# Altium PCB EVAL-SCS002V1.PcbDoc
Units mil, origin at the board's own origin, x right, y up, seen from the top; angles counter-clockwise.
Board outline 1200 x 440 mil, 2 copper layers (Top Layer, Bottom Layer), stack 61.855 mil thick; 32 components, 23 nets, 115 pads, 56 vias.
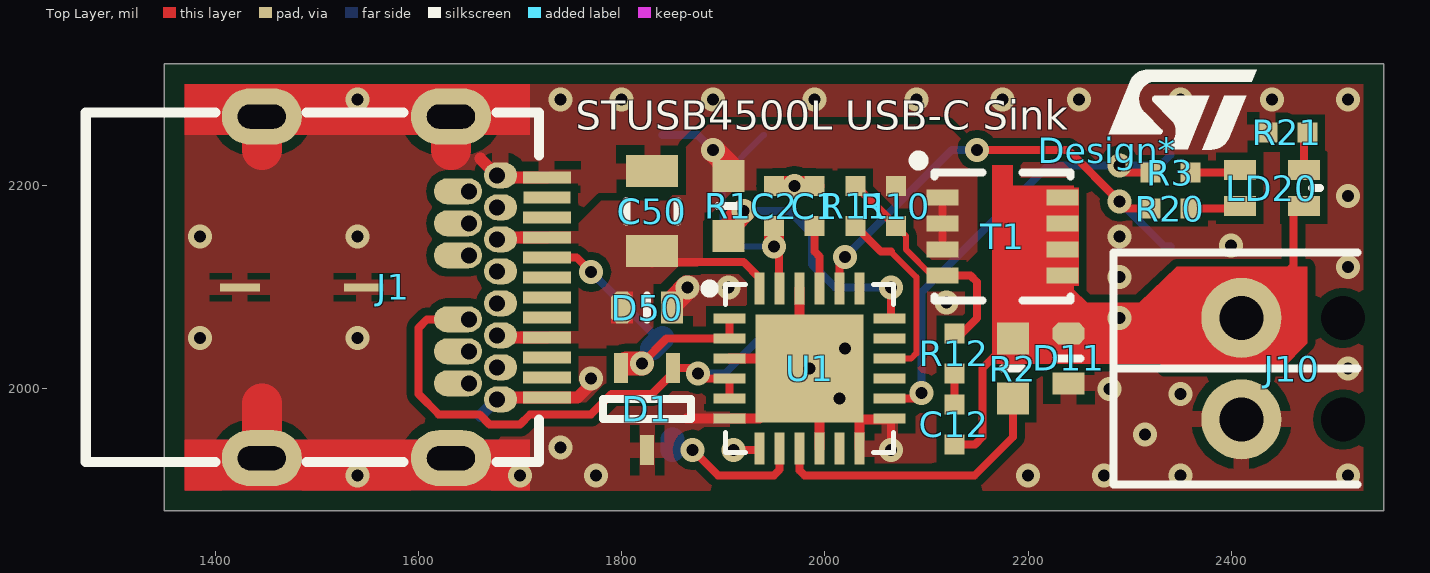
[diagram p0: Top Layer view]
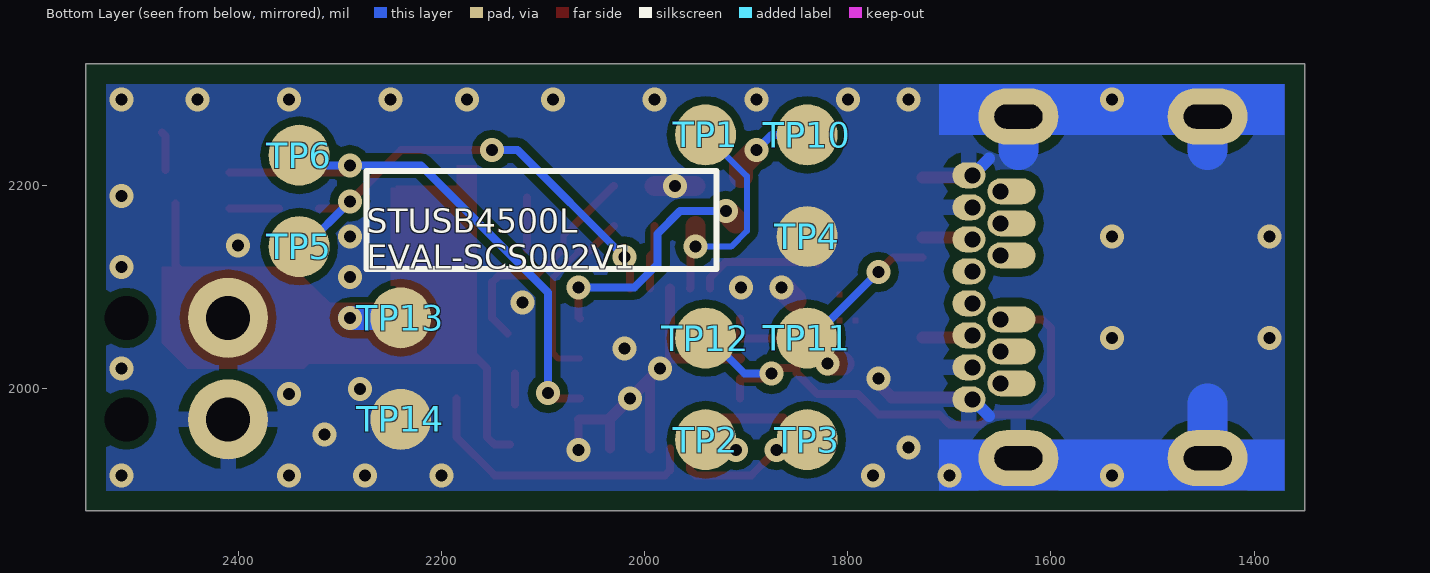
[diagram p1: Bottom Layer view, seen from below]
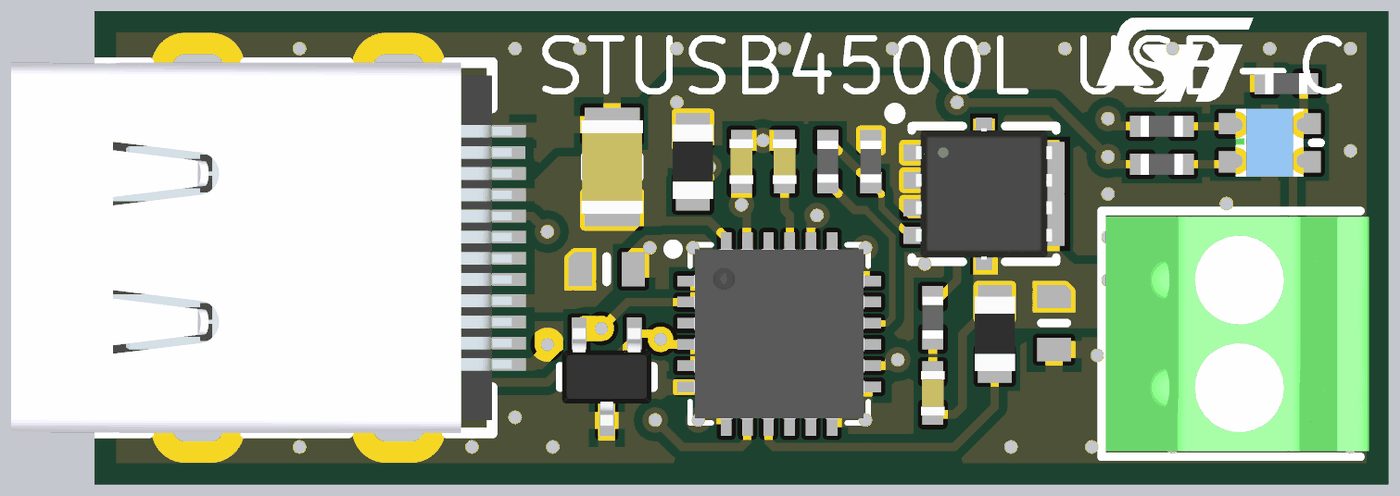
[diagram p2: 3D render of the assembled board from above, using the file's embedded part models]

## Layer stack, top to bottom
Top Solder: solder mask 0.4, Solder Resist, Dk 3.5
Top Layer: signal copper 1.4
Dielectric1: dielectric 59.0551, FR-4, Dk 4.8
Bottom Layer: signal copper 1.4
Bottom Solder: solder mask 0.4, Solder Resist, Dk 3.5

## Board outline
1350,1880 2550,1880 2550,2320 1350,2320

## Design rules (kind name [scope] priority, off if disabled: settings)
Clearance Clearance_USB [(InNet('DP') OR InNet('DM')) vs InNet('GND')] p1: gap=27.56 ignorepadtopadclearanceinfootprint=FALSE except(0: Arc-Hole Track-Hole SMDPad-Hole THPad-Hole Via-Hole Fill-Hole Poly-Hole Region-Hole Text-Hole)
Clearance Clearance_SMPSGND [InNet('GND') vs InNet('SMPSGND')] p2 off: gap=-39.37 ignorepadtopadclearanceinfootprint=FALSE except(0: Arc-Hole Track-Hole SMDPad-Hole THPad-Hole Via-Hole Fill-Hole Poly-Hole Region-Hole Text-Hole)
Clearance Clearance_SMPSGND_PLANE [IsCopperRegion] p3: gap=7.87 ignorepadtopadclearanceinfootprint=FALSE except(0: Arc-Hole Track-Hole SMDPad-Hole THPad-Hole Via-Hole Fill-Hole Poly-Hole Region-Hole Text-Hole)
Clearance [All] p4: gap=5.91 ignorepadtopadclearanceinfootprint=FALSE except(0: Arc-Hole Track-Hole SMDPad-Hole THPad-Hole Via-Hole Fill-Hole Poly-Hole Region-Hole Text-Hole)
ComponentClearance [All] p1 off: gap=10 collisioncheckmode=3 verticalgap=10 showdistances=FALSE
DiffPairsRouting [All] p1: maxlimit=39.37 minlimit=5.91 mostfreqgap=5.91 toplayer_minwidth=5.91 toplayer_maxwidth=118.11 toplayer_prefwidth=15.75 bottomlayer_minwidth=5.91 bottomlayer_maxwidth=118.11 bottomlayer_prefwidth=15.75 maxuncoupledlength=500
HoleSize [All] p1: absolutevalues=TRUE maxlimit=393.7 minlimit=11.81 maxpercent=80.000 minpercent=20.000
MinimumSolderMaskSliver [All] p1: minsoldermaskwidth=1
PlaneClearance PlaneClearance_USB [(InNet('DP') OR InNet('DM'))] p1: clearance=23.62
PlaneClearance [All] p2: clearance=5.91
PlaneConnect [All] p1: planeconnectstyle=Relief reliefexpansion=0 reliefentries=4 reliefconductorwidth=15.75 reliefairgap=5.91
PolygonConnect PolygonConnect_Screw [All vs (HasFootprint('SCREW M3 AND 20MM SPACER'))] p1: connectstyle=Direct reliefconductorwidth=11.81 reliefentries=4 polygonreliefangle="90 Angle" airgapwidth=7.87
PolygonConnect PolygonConnect_VIA [All vs IsVia] p2: connectstyle=Direct reliefconductorwidth=7.87 reliefentries=4 polygonreliefangle="45 Angle" airgapwidth=10
PolygonConnect PolygonConnect_VBUS [All vs InNet('VBUS')] p3: connectstyle=Direct reliefconductorwidth=15.75 reliefentries=4 polygonreliefangle="90 Angle" airgapwidth=10
PolygonConnect PolygonConnect_3V3 [All vs InNet('3V3')] p4: connectstyle=Direct reliefconductorwidth=7.87 reliefentries=4 polygonreliefangle="45 Angle" airgapwidth=10
PolygonConnect PolygonConnect_TP [(InComponentClass('Bottom Side Components'))] p5: connectstyle=Direct reliefconductorwidth=15.75 reliefentries=4 polygonreliefangle="90 Angle" airgapwidth=5.91
PolygonConnect [All] p6: connectstyle=Relief reliefconductorwidth=15.75 reliefentries=4 polygonreliefangle="90 Angle" airgapwidth=9.84
RoutingVias [All] p1: holewidth=11.81 width=23.62 viastyle="Through Hole" minholewidth=11.81 minwidth=23.62 maxholewidth=118.11 maxwidth=196.85
ShortCircuit ShortCircuit_SMPSGND [InNet('SMPSGND') vs InNet('GND')] p1: allowed=TRUE
ShortCircuit ShortCircuit_GNDA3 [InNet('GNDA3') vs InNet('GND')] p2: allowed=TRUE
ShortCircuit ShortCircuit_GNDA4 [InNet('GNDA4') vs InNet('GND')] p3: allowed=TRUE
ShortCircuit ShortCircuit_VCCINT34 [InNet('VCCINT34')] p4: allowed=TRUE
ShortCircuit ShortCircuit_VCCINT70 [InNet('VCCINT70') vs InNet('VCCINT')] p5: allowed=TRUE
ShortCircuit ShortCircuit_VCCINT84 [InNet('VCCINT84') vs InNet('VCCINT')] p6: allowed=TRUE
ShortCircuit ShortCircuit_VCCINT124 [InNet('VCCINT124') vs InNet('VCCINT')] p7: allowed=TRUE
ShortCircuit ShortCircuit_VCCINT138 [InNet('VCCINT138') vs InNet('VCCINT')] p8: allowed=TRUE
ShortCircuit ShortCircuit_VCCINT38 [InNet('VCCINT38') vs InNet('VCCINT')] p9: allowed=TRUE
ShortCircuit ShortCircuit_VCCD3 [InNet('VCCD3') vs InNet('VCCD')] p10: allowed=TRUE
ShortCircuit ShortCircuit_VCCD4 [InNet('VCCD4') vs InNet('VCCD')] p11: allowed=TRUE
ShortCircuit ShortCircuit_VCCA3 [InNet('VCCA3') vs InNet('VCCA')] p12: allowed=TRUE
ShortCircuit ShortCircuit_VCCA4 [InNet('VCCa4') vs InNet('VCCA')] p13: allowed=TRUE
ShortCircuit [All] p14: allowed=FALSE
SilkToSilkClearance [All] p1: silktosilkclearance=0
SilkToSolderMaskClearance [IsPad] p1: minsilkscreentomaskgap=0 clearancetoexposedcopper=TRUE
SolderMaskExpansion SolderMaskExpansion_via [IsVia] p1: expansion=-7.87
SolderMaskExpansion [All] p2: expansion=4
Width [All] p1: maxlimit=393.7 minlimit=5.91 preferedwidth=7.87 minimp=50.000000 maximp=50.000000 favimp=50.000000
21 further rules are at their usual default settings.

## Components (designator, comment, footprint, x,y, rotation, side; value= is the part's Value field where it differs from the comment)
C1 "1µF" CAPC1005N 1990,2180 r270 top
C2 "1µF" CAPC1005N 1950,2180 r270 top
C12 "100nF" CAPC1005N 2127.5,1965 r270 top
C50 "4.7µF" CAPC2012N 1830,2175 r90 top
D1 "ESDA25W" SOT323-3L 1825,1980 r270 top value="25V TRANSIL SOT323"
D11 "ESDA25P35" QFN1610 2240,2030 r90 top value=22V
D50 "ESDA25P35" QFN1610 1825,2080 r180 top value=22V
Design* "Comment" "LOGO - ST - 2mm" 2277.82,2235 r0 top
J1 "USB_3.1_TypeC_Receptacle_1.6mm" "USB3 C - SMT ET T - H - F - WURTH - 632723X00011" 1310,2100 r270 top
J10 "VSNK" MPT_0.5_2-2.54 2410,2020 r180 top
LD20 "RGB" LED_0606_RGB_WURTH 2440,2197.5 r180 top
R1 "1k" RESC1608N 1905,2180 r90 top
R2 "1k" RESC1608N 2185,2020 r270 top
R3 "22k" RESC1005N 2340,2212.93 r180 top
R10 "100k" RESC1005N 2070,2180 r270 top
R11 "22k" RESC1005N 2030,2180 r270 top
R12 "100" RESC1005N 2127.5,2035 r270 top
R20 "22k" RESC1005N 2340,2177.5 r180 top
R21 "33k" RESC1005N 2455.32,2252.5 r180 top
T1 "STL6P3LLH6" POWERFLAT_3.3X3.3_F 2175,2150 r270 top
TP1 "TestPoint" TestPoint_SMD_1.27mm#1 2010,2250 r180 bottom value=TestPoint_SMD
TP2 "TestPoint" TestPoint_SMD_1.27mm#2 1950,1950 r90 bottom value=TestPoint_SMD
TP3 "TestPoint" TestPoint_SMD_1.27mm#2 1850,1950 r90 bottom value=TestPoint_SMD
TP4 "TestPoint" TestPoint_SMD_1.27mm#3 1660,2145 r90 bottom value=TestPoint_SMD
TP5 "TestPoint" TestPoint_SMD_1.27mm#4 2150,2130 r90 bottom value=TestPoint_SMD
TP6 "TestPoint" TestPoint_SMD_1.27mm#4 2150,2220 r90 bottom value=TestPoint_SMD
TP10 "TestPoint" TestPoint_SMD_1.27mm#4 1650,2240 r90 bottom value=TestPoint_SMD
TP11 "TestPoint" TestPoint_SMD_1.27mm#5 1825,2055 r225 bottom value=TestPoint_SMD
TP12 "TestPoint" TestPoint_SMD_1.27mm#2 1950,2050 r90 bottom value=TestPoint_SMD
TP13 "TestPoint" TestPoint_SMD_1.27mm#6 2350,2050 r90 bottom value=TestPoint_SMD
TP14 "TestPoint" TestPoint_SMD_1.27mm#7 2250,1780 r90 bottom value=TestPoint_SMD
U1 "STUSB4500L" "QFN24 - 4X4MM - PITCH 0.5MM - EXPOSEDPAD" 1985,2020 r0 top value=STUSB4500

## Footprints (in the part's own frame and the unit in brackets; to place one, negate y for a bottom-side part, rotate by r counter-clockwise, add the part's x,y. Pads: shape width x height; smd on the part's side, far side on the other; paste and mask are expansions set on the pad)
CAPC1005N [mm] "Chip Capacitor, Body 1.0x0.5mm, IPC Medium Density"
  rect 0.5x0.5 smd: 1(-0.5,0) 2(0.5,0)
  body extent -0.52,-0.27 0.53,0.28, height 0.55
CAPC2012N [mm] "Chip Capacitor, Body 2.0x1.3mm, IPC Medium Density"
  rect 0.8x1.3 smd: 1(-1,0) 2(1,0)
  silkscreen extent -0.25,-0.64 0.25,0.64, body extent -1.1,-0.72 1.1,0.73, height 1.35
LED_0606_RGB_WURTH [mm] "Chip; Body 1.6 x 1.6 mm (LxW typ) WURTH"
  rect 0.8x0.5 smd: A(-0.8,0.45) BK(-0.8,-0.45) GK(0.8,-0.45) RK(0.8,0.45)
  silkscreen extent -1.2,0 -1,0, body extent -0.8,-0.8 0.8,0.8, height 0.4
"LOGO - ST - 2mm" [mil]
  silkscreen extent 1,1 147,79
MPT_0.5_2-2.54 [mm] "Screw  PCB terminal block, 2 positions 2.54mm pitch"
  round 0 hole 1.1: 01(-2.54,1.27) 02(-2.54,-1.27)
  round 2 hole 1.1: 1(0,1.27) 2(0,-1.27)
  silkscreen extent -2.9,-2.9 3.2,2.9, body extent -3.1,-2.77 3.1,2.77, height 8.5
POWERFLAT_3.3X3.3_F [mm] "PowerFLAT™ 3.3 x 3.3 type F"
  rect 0.4x0.8 smd: 1(-0.975,-1.5) 2(-0.325,-1.5) 3(0.325,-1.5) 4(0.975,-1.5) 5(0.975,1.5) 6(0.325,1.5) 7(-0.325,1.5) 8(-0.975,1.5)
  Top Layer region: 0,1.9 1.225,1.9 1.225,0.2 1.775,0.2 1.775,-0.2 0,-0.2
  Top Layer region: 0,1.9 -1.225,1.9 -1.225,0.2 -1.775,0.2 -1.775,-0.2 0,-0.2
  silkscreen extent -2.02,-2.22 1.6,1.7, body extent -1.55,-1.6 1.55,1.6, height 0.8
"QFN24 - 4X4MM - PITCH 0.5MM - EXPOSEDPAD" [mm] "QFN24 - 4X4mm - pitch 0.5mm - ExposedPAD"
  rect 2.7x2.7 smd: 0(0,0)
  rect 0.8x0.25 smd: 1(-2,1.25) 2(-2,0.75) 3(-2,0.25) 4(-2,-0.25) 5(-2,-0.75) 6(-2,-1.25) 13(2,-1.25) 14(2,-0.75) 15(2,-0.25) 16(2,0.25) 17(2,0.75) 18(2,1.25)
  rect 0.25x0.8 smd: 7(-1.25,-2) 8(-0.75,-2) 9(-0.25,-2) 10(0.25,-2) 11(0.75,-2) 12(1.25,-2) 19(1.25,2) 20(0.75,2) 21(0.25,2) 22(-0.25,2) 23(-0.75,2) 24(-1.25,2)
  silkscreen extent -2.6,-2.1 2.1,2.1, body extent -2,-2 2,2, height 1
QFN1610 [mm] "QFN 1610"
  oct 0.55x0.8 smd paste+0 mask+0.1: 1(0.625,0)
  rect 0.55x0.8 smd: 2(-0.625,0)
  Top Layer region: 0.35,0.25 0.5,0.25 0.5,0.4 0.35,0.4
  Top Layer region: 0.5,-0.4 0.5,-0.25 0.35,-0.25 0.35,-0.4
  Top Layer region: 0.75,0.4 0.75,0.25 0.9,0.25 0.9,0.4
  silkscreen extent 0,-0.3 0,0.3, body extent -0.8,-0.5 0.8,0.5, height 0.55
RESC1005N [mm] "Chip Resistor, Body 1.0x0.5mm, IPC Medium Density"
  rect 0.5x0.5 smd: 1(-0.5,0) 2(0.5,0)
  body extent -0.5,-0.25 0.5,0.25, height 0.35
RESC1608N [mm] "Chip Resistor, Body 1.6x0.8mm, IPC Medium Density"
  rect 0.8x0.8 smd: 1(-0.75,0) 2(0.75,0)
  silkscreen extent 0,-0.25 0,0.25, body extent -0.87,-0.47 0.88,0.48, height 0.55
SOT323-3L [mm] "SOT323, 3-Leads, Body 2.2x2.4mm (max), Pitch 0.65mm, IPC Medium Density"
  rect 0.75x0.35 smd: 1(-1.025,0.65) 2(-1.025,-0.65) 3(1.025,0)
  silkscreen extent -0.25,-1.1 0.25,1.1, body extent -1.15,-1.05 1.15,1.05, height 1
TestPoint_SMD_1.27mm#1 [mil] "TestPoint_SMD_1.27mm"
  round 60 smd paste-39.37 mask-5: 0(70,0)
TestPoint_SMD_1.27mm#2 [mil] "TestPoint_SMD_1.27mm"
  round 60 smd paste-39.37 mask-5: 0(0,-10)
TestPoint_SMD_1.27mm#3 [mil] "TestPoint_SMD_1.27mm"
  round 60 smd paste-39.37 mask-5: 0(5,180)
TestPoint_SMD_1.27mm#4 [mil] "TestPoint_SMD_1.27mm"
  round 60 smd paste-39.37 mask-5: 0(10,190)
TestPoint_SMD_1.27mm#5 [mil] "TestPoint_SMD_1.27mm"
  round 60 smd paste-39.37 mask-5: 0(-7.07,-14.14)
TestPoint_SMD_1.27mm#6 [mil] "TestPoint_SMD_1.27mm"
  round 60 smd paste-39.37 mask-5: 0(20,-110)
TestPoint_SMD_1.27mm#7 [mil] "TestPoint_SMD_1.27mm"
  round 60 smd paste-39.37 mask-5: 0(190,-10)
"USB3 C - SMT ET T - H - F - WURTH - 632723X00011" [mm] "USB3 type C - montage sur CI - Femmelle - Angle droit - Composant Certifié (x=1 -> PCB height= 1mm TID : 5,200,000,115 // x=3 -> PCB height= 1mm TID : 5,200,000,116)"
  rect 0.3x1.2 smd mask+0: A1(-2.75,10.58) A3(-1.75,10.58) A4(-1.25,10.58) A5(-0.75,10.58) A8(0.75,10.58) A9(1.25,10.58) A10(1.75,10.58) A11(2.25,10.58) A12(2.75,10.58)
  rect 0.3x1.168 smd mask+0: A2(-2.25,10.58)
  rect 0.3x1.199 smd mask+0: A6(-0.25,10.58) A7(0.25,10.58)
  oval 0.65x0.825 hole 0.4 copper offset 0,0.088 mask+0: B1(2.8,9.33) B4(1.2,9.33) B6(0.4,9.33) B7(-0.4,9.33) B9(-1.2,9.33) B12(-2.8,9.33) G1(-2,9.33) G2(2,9.33)
  oval 0.65x1.2 hole 0.4 copper offset 0,-0.275 mask+0: B2(2.4,8.63) B3(1.6,8.63) B5(0.8,8.63) B8(-0.8,8.63) B10(-1.6,8.63) B11(-2.4,8.63)
  rect 0.2x1 smd: G3(0,6) G4(0,2.9)
  oval 1.4x2 hole 0.6 slot 1.2 at 90 deg: G5(-4.27,8.18) G6(4.27,8.18) G7(-4.27,3.45) G8(4.27,3.45)
  silkscreen extent -4.37,-0.95 4.37,10.38, body extent -4.37,-0.95 4.37,10.84, height 2.97

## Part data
C1 C2: library part C_1uF_X5R_6V3_20p_0402, "Capacitor 1µF X5R 6V3 20% 0402", Manufacturer="Würth Elektronik"
C12: library part C_100nF_X5R_25V_20p_0402, "Capacitor 100nF X5R 25V 20% 0402", Manufacturer="Würth Elektronik"
C50: library part C_4.7uF_X7R_25V_20p_0805, "Capacitor 4.7µF X7R 25V 20% 0805", Manufacturer="Würth Elektronik"
D1: "Dual Transil Array For ESD Protection in SOT323 Vbr = 25V", Manufacturer=STMicroelectronics, Part Number="Dual Transil Array For ESD Protection in SOT323 Vbr {} 25V"
D11 D50: library part ESDA25P35-1U1M, "High power transient voltage suppressor Vbr = 24.6V", Manufacturer=STMicroelectronics, Part Number="High power transient voltage suppressor Vbr {} 24.6"
J1: "USB 3.1 Type C Receptacle Horizontal THR WR-COM 1.6mm PCB thickness", Manufacturer="Würth Elektronik"
J10: library part MPT_0.5_2-2.54, "2 way PCB vertical mount SCREW terminal, 2.54mm", Alternate Manufacturer="Phoenix Contact", Alternate Manufacturer Code="MPT 0.5/2-2.54", Manufacturer="Würth Elektronik"
LD20: library part Led_RGB_0606, "RGB Led 1.6 x 1.6 mm Diffused", Manufacturer="Würth Elektronik"
R1 R2: library part R_0603_5percent, "5% 0603 SMD resistor", Tolerance=5%
R3 R10 R11 R12 R20 R21: library part R_0402_5percent, "5% 0402 SMD resistor", Tolerance=5%
T1: "P-channel 40 V, 0.0175 O typ.,8 A, STripFET™ F6  Power MOSFET in a PowerFLAT™ 3.3 x 3.3 package", Manufacturer=STMicroelectronics, Part Number="P-channel 30 V, 0.024 Ohm typ., 6 A STripFET H6 Power MOSFET in a PowerFLAT 3.3 x 3.3 package"
TP1 TP2 TP3 TP4 TP5 TP6 TP10 TP11 TP12 TP13 TP14: library part TestPoint_SMD, "TestPoint_SMD"
U1: library part STUSB4500LQTR, "Standalone USB TypeC controller in QFN24 4x4mm", Manufacturer=STMicroelectronics, Part Number="Standalone USB PD controller  with SINK auto-run mode in QFN24 4x4mm"

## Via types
v1: diameter 23.62, hole 11.81, Top Layer to Bottom Layer, tented top, 50 vias
v2: diameter 23.62, hole 11.81, Top Layer to Bottom Layer, 6 vias

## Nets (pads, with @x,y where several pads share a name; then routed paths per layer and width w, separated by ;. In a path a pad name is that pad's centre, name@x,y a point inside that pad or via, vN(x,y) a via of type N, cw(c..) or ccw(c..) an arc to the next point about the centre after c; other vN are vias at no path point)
2V7: C2.2 TP1.0 U1.23 | length 232.3
  Top Layer w7.87: v1(1950,2140) 1955,2135 1955,2099.21 U1.23
  Top Layer w19.68: v1(1950,2140) C2.2
  Bottom Layer w5.91: TP1.0 1899.33,2209.33 1899.33,2155.41 1914.75,2140 v1(1950,2140)
A_B_SIDE: U1.17
ALERT#: U1.19
ATTACH: U1.11
CC1: D1.2 J1.A5 TP11.0 U1.1 U1.2 | length 291.9
  Top Layer w7.87: J1.A5 1755.47,2129.53 v1(1770,2115) ; v2(1820,2025) 1820,2025.34 1844.19,2049.53 U1.2 U1.1
  Top Layer w23.62: D1.2@1805,2025 v2(1820,2025)
  Bottom Layer w7.87: v1(1770,2115) 1835,2050 TP11.0
  Bottom Layer w23.62: TP11.0@1830,2040 TP11.0
CC2: D1.1 J1.B5 TP12.0 U1.4 U1.5 | length 566.1
  Top Layer w7.87: J1.B5 1608.5,2068.5 1600,2060 1600,1995 1620,1975 1660,1975 1670,1965 1700,1965 1710,1975 1770,1975 1790,1995 1830,1995 1850.59,2015.59 D1.1 1869.65,2020.35 v2(1875,2015) 1879.84,2010.16 U1.4 U1.5
  Bottom Layer w7.87: v2(1875,2015) 1901.48,2015 1936.48,2050 TP12.0
DISCH: R2.2 U1.9 | length 286.8
  Top Layer w7.87: U1.9 1975.16,1919.84 1980,1915 2147.5,1915 2185,1952.5 R2.2
GND: C1.1 C2.1 C50.2 D1.3 D11.2 D50.2 J1.A1 J1.A12 J1.B1 J1.B12 J1.G1 J1.G2 J1.G3 J1.G4 J1.G5 J1.G6 J1.G7 J1.G8 J10.1 R21.2 TP4.0 TP14.0 U1.0 U1.3 U1.6 U1.10 U1.12 U1.13 U1.22 | length 967
  Top Layer w7.87: U1.13 2064.53,1970 2065,1969.53 v1(2065,1940)
  Top Layer w9.84: 1863.9,1970.79 U1.6 U1.0@1935.79,1970.79 ; U1.3 U1.0@1975.16,2029.84 ; U1.22 U1.0@1975.16,2029.84 ; v2(1985,2020) U1.0@1975.16,2029.84 ; U1.10 U1.0@1994.84,2010.16 ; U1.12 U1.0@2034.21,1970.79 ; U1.0@2035,1970 U1.13@2064.53,1970
  Top Layer w11.81: 1661,2226.56 J1.B12 ; J1.B1 1679.29,1991.73 J1.A12 1756.73,1991.73 v2@1770,2005 ; J1.B12@1679.29,2208.27 J1.A1 ; v2(1985,2020) 1994.84,2010.16 2034.21,1970.79 U1.0@2035,1970
  Top Layer w19.68: C2.1 v1(1970,2199.68) C1.1
  Top Layer w23.62: D50.2@1852.5,2087.5 v1(1865,2100)
  Top Layer w39.37: J1.G8 1445.83,1985.83 ; 1445.83,2235 J1.G7 ; 1632.05,2235 J1.G5
  Bottom Layer w11.81: 1661.02,1973.46 J1.B1 ; 1661,2226.56 J1.B12
  Bottom Layer w39.37: J1.G8 1445.83,1985.83 ; 1445.83,2235 J1.G7 ; 1632.05,2235 J1.G5
  other v1: 1540,1915 1700,1915 1775,1915 2200,1915 2275,1915 2350,1915 2515,1915 1740,1942.5 2315,1955 2350,1995 2280,2000 2515,2020 1385,2050 1540,2050 2120,2085 1905,2100 2290,2110 2515,2120 2400,2141.06 1385,2150 1540,2150 2290,2150 2515,2190 1540,2285 1740,2285 1800,2285 1890,2285 1990,2285 2090,2285 2175,2285 2250,2285 2350,2285 2440,2285 2515,2285
  other v2: 2014.53,1990.47 1770,2010 2020,2040
GPIO: U1.15
NetC1_2: C1.2 U1.21 | length 63.6
  Top Layer w7.87: C1.2 1990,2135.16 1994.84,2130.32 U1.21
NetC12_1: C12.1 R12.2 | length 30.6
  Top Layer w7.87: C12.1 R12.2
NetLD20_BK: LD20.BK R21.1 | length 38.7
  Top Layer w7.87: LD20.BK 2471.5,2249 R21.1
NetLD20_GK: LD20.GK R3.1 | length 48.8
  Top Layer w7.87: R3.1 LD20.GK@2408.5,2212.93
NetLD20_RK: LD20.RK R20.1 | length 48.8
  Top Layer w7.87: R20.1 LD20.RK@2408.5,2177.5
NetR1_1: R1.1 U1.18 | length 244.1
  Top Layer w7.87: U1.18 2065,2070.47 v1(2065,2100)
  Top Layer w23.62: R1.1@1910,2165 v1(1920,2175)
  Bottom Layer w7.87: v1@1915,2175 v1(1920,2175) 1965,2175 1987.5,2152.5 1987.5,2122.5 2010,2100 v1(2065,2100)
NetR10_2: R10.2 R11.1 R12.1 T1.4 | length 223.5
  Top Layer w5.91: R10.2 2080,2150.32 2080,2137 2105.39,2111.61 T1.4@2107.87,2111.61
  Top Layer w7.87: R11.1 2030.63,2199.68 R10.2 ; T1.4@2107.87,2111.61 T1.4 2143.39,2111.61 2150,2105 2150,2069.68 R12.1@2135,2054.68
NetR11_2: R11.2 U1.16 | length 184.2
  Top Layer w5.91: U1.16 2084.84,2029.84 2090,2035 2090,2110 2065,2135
  Top Layer w7.87: R11.2 2055.32,2135 2065,2135
RP_1A5: R20.2 TP5.0 U1.20 | length 492.4
  Top Layer w7.87: U1.20 2014.53,2124.53 v1(2020,2130) ; v1(2150,2235) 2239.57,2235 v1(2290,2184.57) 2297.03,2177.54 R20.2 ; v1@2297.5,2177.5 R20.2
  Bottom Layer w7.87: v1(2020,2130) 2125,2235 v1(2150,2235) ; v1(2290,2184.57) 2334.57,2140 TP5.0
RP_3A: R3.2 TP6.0 U1.14 | length 468
  Top Layer w7.87: U1.14 2089.53,1990.47 v1(2095,1995.94) ; v1(2290,2220) 2297.03,2212.97 R3.2@2320.32,2212.97
  Bottom Layer w7.87: v1(2095,1995.94) 2095,2095 2220,2220 v1(2290,2220) 2326.89,2220 2328.44,2218.44 TP6.0
SCL: TP2.0 U1.7 | length 31.3
  Top Layer w7.87: v1@1905,1940 1934.53,1940 U1.7
  other v1: 1910,1940
SDA: TP3.0 U1.8 | length 121.8
  Top Layer w7.87: v1@1875,1935 1895,1915 1950,1915 1955.47,1920.47 U1.8
  Bottom Layer w23.62: TP3.0@1850,1940 TP3.0@1850,1950
  other v1: 1870,1940
VBUS: C50.1 D50.1 J1.A4 J1.A9 J1.B4 J1.B9 R1.2 R10.1 T1.1 T1.2 T1.3 TP10.0 U1.24 | length 362.4
  Top Layer w7.87: C50.1@1830,2123.66 1831.22,2124.88 1920.12,2124.88 1935.79,2109.21 U1.24 ; T1.3 T1.2 T1.1
  Top Layer w11.81: J1.B4 1679.29,2050.79 J1.A9 ; J1.B9 1679.29,2149.21 J1.A4
  Top Layer w23.62: v1(1890,2235) 1905,2220 R1.2
  Bottom Layer w7.87: TP10.0 1875,2250 v1(1890,2235)
VSNK: C12.2 D11.1 J10.2 LD20.A R2.1 T1.5 T1.6 T1.7 T1.8 TP13.0 | length 251.2
  Top Layer w7.87: C12.2@2132.5,1945.32 2147.82,1945.32 2155,1952.5 2155,2020 2170,2035 R2.1@2180,2035 ; 2450,2110 2461.5,2121.5 LD20.A@2461.5,2182.28
  Bottom Layer w23.62: TP13.0 v1(2290,2070)
pads on no net: J1.A2 J1.A3 J1.A6 J1.A7 J1.A8 J1.A10 J1.A11 J1.B2 J1.B3 J1.B6 J1.B7 J1.B8 J1.B10 J1.B11 J10.01 J10.02

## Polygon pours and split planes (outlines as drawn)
GND on Bottom Layer "Bottom Layer-GND" (solid, pour order 10): 1370,2300 2530,2300 2530,1900 1370,1900
GND on Top Layer "Top Layer-GND" (solid, pour order 8): 1370,2300 2530,2300 2530,1900 1370,1900
VBUS on Top Layer "Top Layer-VBUS" (solid, pour order 6): 1755,2160 1780,2185 1845,2185 1850,2190 1850,2225 1885,2260 2120,2260 2150,2230 2150,2135 2140,2125 2105,2125 2085,2145 2085,2170 2080,2175 2060,2175 2020,2215 1960,2215 1940,2195 1910,2195 1880,2165 1880,2125 1875,2120 1855,2120 1835,2100 1835,2065 1810,2040 1700,2040 1700,2060 1755,2060 1755,2140 1700,2140.13 1700,2160

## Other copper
Top Layer:
  region net GND: 1710,1950 1370,1950 1370,1900 1710,1900
  rectangle net GND: 1370,2250 1710,2300
  region net VSNK: 2165,2220 2165,2025 2330,2025 2335,2020 2450,2020 2475,2045 2475,2120 2346.5,2120 2309.25,2085 2258.25,2085 2245,2097.5 2245,2200 2185,2200 2185,2220
  text "Top Layer" at 1400,2450 h39.37
Bottom Layer:
  rectangle net GND: 1370,2250 1710,2300
  region net GND: 1710,1950 1370,1950 1370,1900 1710,1900
  text "Bottom Layer" at 2500,2450 h39.37

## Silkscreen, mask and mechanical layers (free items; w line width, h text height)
Top Overlay:
  text "Top Overlay" at 1400,2450 h39.37
  text "STUSB4500L USB-C Sink" at 1755,2245 h49.21
Bottom Overlay:
  lines w5.91: 1929.13,2118.11 1929.13,2214.57 2273.62,2214.57 2273.62,2118.11 1929.13,2118.11
  text "Bottom Overlay" at 2500,2450 h39.37
  text "STUSB4500L / EVAL-SCS002V1" at 2273.62,2118.11 h23.62
Top Paste:
  text "Top Paste" at 1400,2450 h39.37
Bottom Paste:
  text "Bottom Paste" at 2500,2450 h39.37
Top Solder:
  text "Top Solder" at 1400,2450 h39.37
Bottom Solder:
  text "Bottom Solder" at 2500,2450 h39.37
  text "VBUS" at 1792.5,2237.5 h23.62
  text "2V7" at 2050,2237.5 h23.62
  text "RP_3A" at 2497.5,2222.5 h23.62
  text "RP_1A5" at 2495,2172.5 h23.62
  text "GND" at 1805,2145 h23.62
  text "CC2" at 2045,2060 h23.62
  text "VSNK" at 2198.94,2037.01 h23.62
  text "CC1" at 1795,2035 h23.62
  text "SDA" at 1800,1965 h23.62
  text "GND" at 2200,1957.5 h23.62
  text "SCL" at 2045,1940 h23.62
Drill Guide:
  text "Drill Guide" at 1400,2450 h39.37
Mechanical 1:
  the board outline again, w7.87
Mechanical 4:
  text "Dimensions" at 1400,2450 h39.37
Mechanical 6:
  lines w3.94: 1125,1800 2650,1800 2650,2575 1125,2575 1125,1800
Mechanical 15:
  text "Top Asssembly" at 1400,2450 h39.37
Mechanical 16:
  text "Bottom Asssembly" at 2500,2450 h39.37
Drill Drawing:
  lines w10: 844.97,1216.48 858.77,1216.48 858.77,1202.68 886.38,1202.68 886.38,1216.48 900.19,1216.48 900.19,1244.1 886.38,1244.1 886.38,1257.9 858.77,1257.9 858.77,1244.1 844.97,1244.1 844.97,1216.48 ; 844.97,1326.93 844.97,1340.73 858.77,1354.54 844.97,1368.35 844.97,1382.15 858.77,1382.15 872.58,1368.35 886.38,1382.15 900.19,1382.15 900.19,1368.35 886.38,1354.54 900.19,1340.73 900.19,1326.93 886.38,1326.93 872.58,1340.73 858.77,1326.93 844.97,1326.93 ; 844.97,1451.18 872.58,1464.98 900.19,1451.18 886.38,1478.79 900.19,1506.4 872.58,1492.6 844.97,1506.4 858.77,1478.79 844.97,1451.18 ; 844.97,1603.04 872.58,1575.43 900.19,1603.04 872.58,1630.65 844.97,1603.04
  lines w15: 794.9,1165.4 3415.34,1165.4 ; 794.9,1662.4 3415.34,1662.4 ; 1114.09,1041.15 1114.09,1786.65 ; 1376.24,1041.15 1376.24,1786.65 ; 1736.51,1041.15 1736.51,1786.65 ; 2285.91,1041.15 2285.91,1786.65 ; 2835.31,1041.15 2835.31,1786.65 ; 3082.84,1041.15 3082.84,1786.65 ; 794.9,1041.15 3415.34,1041.15 3415.34,1786.65 794.9,1786.65 794.9,1041.15
  text "Symbol" at 869.45,1699.68 h72
  text "Count" at 1151.36,1699.68 h72
  text "Hole Type" at 1413.51,1699.68 h72
  text "Hole Size" at 1773.78,1699.68 h72
  text "Hole Length" at 2323.18,1699.68 h72
  text "Plated" at 2872.58,1699.68 h72
  text "Via/Pad" at 3120.11,1699.68 h72
  text "56" at 1151.36,1575.43 h60
  text "Round" at 1413.51,1575.43 h60
  text "11.81mil (0.300mm)" at 1773.78,1575.43 h60
  text "-" at 2323.18,1575.43 h60
  text "PTH" at 2872.58,1575.43 h60
  text "Via" at 3120.11,1575.43 h60
  text "14" at 1151.36,1451.18 h60
  text "Round" at 1413.51,1451.18 h60
  text "15.75mil (0.400mm)" at 1773.78,1451.18 h60
  text "-" at 2323.18,1451.18 h60
  text "PTH" at 2872.58,1451.18 h60
  text "Pad" at 3120.11,1451.18 h60
  text "4" at 1151.36,1326.93 h60
  text "Round" at 1413.51,1326.93 h60
  text "43.31mil (1.100mm)" at 1773.78,1326.93 h60
  text "-" at 2323.18,1326.93 h60
  text "PTH" at 2872.58,1326.93 h60
  text "Pad" at 3120.11,1326.93 h60
  text "4" at 1151.36,1202.68 h60
  text "Slot" at 1413.51,1202.68 h60
  text "23.62mil (0.600mm)" at 1773.78,1202.68 h60
  text "47.24mil (1.200mm)" at 2323.18,1202.68 h60
  text "PTH" at 2872.58,1202.68 h60
  text "Pad" at 3120.11,1202.68 h60
  text "78 Total" at 1151.36,1078.43 h60
  text "Slot definitions :" at 869.45,991.45 h60
  text "Routed Path Length" at 1278.58,991.45 h60
  text "= Calculated from tool start centre position to tool end centre position." at 1785.4,991.45 h60
  text "Hole Length" at 1278.58,941.75 h60
  text "= Routed Path Length + Tool Size = Slot length as defined in the PCB layout" at 1597.3,941.75 h60
Mechanical 17:
  text "Bottom Assembly" at 2500,2450 h39.37

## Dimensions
1350,1880 to 1350,2320 on Mechanical 2
1350,1880 to 2550,1880 on Mechanical 2
1350,2320 to 2550,2320 on Mechanical 4
1350,2320 to 1350,1880 on Mechanical 4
